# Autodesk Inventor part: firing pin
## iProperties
Created: 2006-04
Part Number: firing pin
Document SubType Name: Modeling
Designer: Калинин
Author: Калинин
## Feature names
1. Вращение1 [Revolution]
